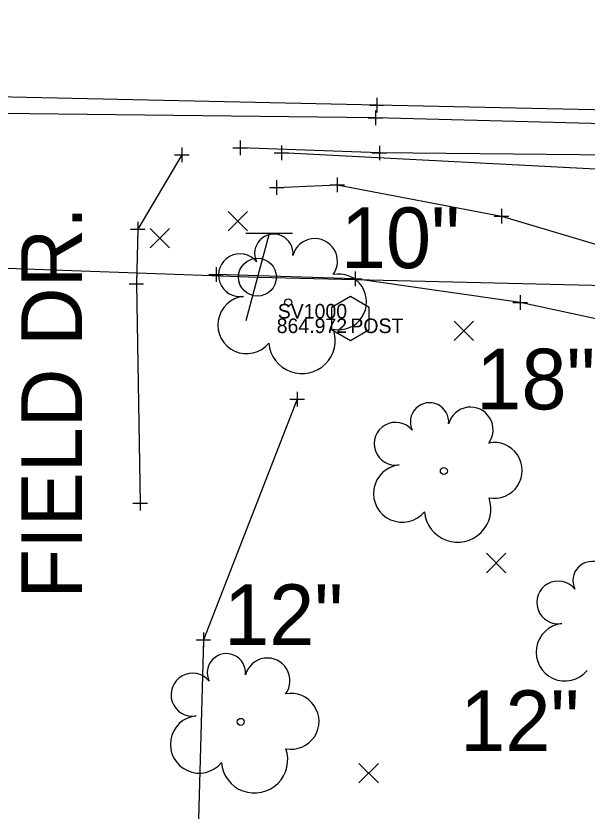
# Model space of a CAD drawing. Extents: x 2005176 to 2005823, y 572472 to 572942.
# Drawn here: x 2005452.2 to 2005491.4, y 572551.1 to 572605.7 of the extents above; entities that cross this region are included whole.
import ezdxf

# ---------------------------------------------------------------- set-up
doc = ezdxf.new("R2010")
doc.units = 0
for name, color, linetype in [('DR_X_Text', 7, 'Continuous'), ('DV_X_Property_Line', 7, 'Continuous'), ('GE_X_Alignment_100_Bearings', 7, 'Continuous'), ('GE_X_Alignment_100_Curve_Data', 7, 'Continuous'), ('GE_X_Alignment_100_Distances', 7, 'Continuous'), ('GE_X_Alignment_100_Stations', 7, 'Continuous'), ('GE_X_Alignment_500_Bearings', 7, 'Continuous'), ('PV_X_COP', 7, 'Continuous'), ('SC_Scratch1', 7, 'Continuous'), ('SC_Scratch10', 7, 'Continuous'), ('SC_Scratch8', 7, 'Continuous'), ('SV_P_Mon_Cells_Set', 7, 'Continuous'), ('SV_X_Control_Cells_Found', 7, 'Continuous'), ('SV_X_Mon_Cells_Found', 7, 'Continuous'), ('SV_X_Random_Point', 7, 'Continuous'), ('SV_X_Shot_Marker', 7, 'Continuous'), ('UT_X_Overhead_Telecom', 7, 'Continuous'), ('VG_X_Text', 7, 'Continuous')]:
    doc.layers.add(name, color=color, linetype=linetype)

msp = doc.modelspace()

# ---------------------------------------------------------------- linework, layer by layer
at = {"layer": 'GE_X_Alignment_100_Bearings'}
msp.add_lwpolyline([(2005818.636, 572588.972), (2005775.196, 572590.402), (2005728.29, 572591.88), (2005676.677, 572593.613), (2005626.55, 572595.194), (2005577.828, 572596.717), (2005526.97, 572598.442), (2005477.007, 572599.528), (2005423.668, 572600.697), (2005368.746, 572601.993), (2005321.745, 572602.994), (2005266.716, 572604.351), (2005220.033, 572605.659)], dxfattribs=at)
at = {"layer": 'GE_X_Alignment_100_Curve_Data'}
msp.add_lwpolyline([(2005463.609, 572596.115), (2005460.593, 572591.02), (2005460.492, 572587.254), (2005460.751, 572572.197)], dxfattribs=at)
at = {"layer": 'GE_X_Alignment_100_Distances'}
msp.add_lwpolyline([(2005818.697, 572589.047), (2005775.196, 572590.402), (2005728.29, 572591.88), (2005676.677, 572593.613), (2005626.55, 572595.194), (2005577.828, 572596.717), (2005526.97, 572598.442), (2005477.007, 572599.528), (2005423.668, 572600.697), (2005368.746, 572601.993), (2005321.745, 572602.994), (2005266.716, 572604.351), (2005220.057, 572605.648)], dxfattribs=at)
at = {"layer": 'GE_X_Alignment_100_Stations'}
msp.add_lwpolyline([(2005470.12, 572593.875), (2005474.272, 572594.058), (2005485.559, 572591.913), (2005494.153, 572589.341), (2005502.252, 572586.105)], dxfattribs=at)
at = {"layer": 'GE_X_Alignment_500_Bearings'}
for points in [[(2005547.792, 572586.884), (2005537.69, 572587.6), (2005528.11, 572586.874), (2005517.957, 572586.766), (2005507.009, 572591.458), (2005495.082, 572594.973), (2005470.451, 572596.25)], [(2005496.157, 572583.959), (2005486.828, 572585.976), (2005475.498, 572587.61), (2005465.973, 572587.901)], [(2005471.535, 572579.333), (2005465.091, 572562.814), (2005464.598, 572544.768), (2005464.708, 572532.148), (2005458.479, 572515.558)]]:
    msp.add_lwpolyline(points, dxfattribs=at)
at = {"layer": 'PV_X_COP'}
msp.add_lwpolyline([(2005473.882, 572584.129), (2005475.18, 572583.379), (2005476.478, 572584.129), (2005476.478, 572585.629), (2005475.18, 572586.379), (2005473.882, 572585.629), (2005473.882, 572584.129)], dxfattribs=at)
at = {"layer": 'SC_Scratch1'}
for p, q in [((2005469.604, 572590.72), (2005467.998, 572584.72)), ((2005471.204, 572590.72), (2005468.004, 572590.72))]:
    msp.add_line(p, q, dxfattribs=at)
msp.add_circle((2005468.801, 572587.72), 1.3, dxfattribs=at)
at = {"layer": 'SC_Scratch10'}
msp.add_lwpolyline([(2005818.546, 572585.941), (2005774.935, 572587.721), (2005728.191, 572589.228), (2005676.714, 572591.115), (2005626.893, 572592.621), (2005577.772, 572593.782), (2005527.621, 572595.745), (2005477.172, 572596.247), (2005467.62, 572596.601)], dxfattribs=at)
at = {"layer": 'SC_Scratch8'}
msp.add_lwpolyline([(2005818.664, 572586.636), (2005775.011, 572588.281), (2005728.162, 572589.789), (2005676.746, 572591.584), (2005626.726, 572593.575), (2005577.921, 572595.757), (2005527.418, 572597.322), (2005476.909, 572598.652), (2005423.434, 572599.267), (2005368.772, 572600.603), (2005321.591, 572601.671), (2005267.034, 572602.727), (2005220.031, 572603.934)], dxfattribs=at)
at = {"layer": 'SV_P_Mon_Cells_Set'}
for p, q in [((2005477.007, 572600.028), (2005477.007, 572599.028)), ((2005477.007, 572600.028), (2005477.007, 572599.028)), ((2005476.507, 572599.528), (2005477.507, 572599.528)), ((2005476.507, 572599.528), (2005477.507, 572599.528)), ((2005477.007, 572599.528), (2005477.007, 572599.528)), ((2005477.007, 572599.528), (2005477.007, 572599.528)), ((2005476.909, 572599.152), (2005476.909, 572598.152)), ((2005476.409, 572598.652), (2005477.409, 572598.652)), ((2005476.909, 572598.652), (2005476.909, 572598.652)), ((2005467.62, 572597.101), (2005467.62, 572596.101)), ((2005470.451, 572596.75), (2005470.451, 572595.75)), ((2005477.172, 572596.747), (2005477.172, 572595.747)), ((2005463.109, 572596.115), (2005464.109, 572596.115)), ((2005463.609, 572596.615), (2005463.609, 572595.615)), ((2005463.609, 572596.115), (2005463.609, 572596.115)), ((2005467.12, 572596.601), (2005468.12, 572596.601)), ((2005467.62, 572596.601), (2005467.62, 572596.601)), ((2005469.951, 572596.25), (2005470.951, 572596.25)), ((2005470.451, 572596.25), (2005470.451, 572596.25)), ((2005476.672, 572596.247), (2005477.672, 572596.247)), ((2005477.172, 572596.247), (2005477.172, 572596.247)), ((2005474.272, 572594.558), (2005474.272, 572593.558)), ((2005470.12, 572594.375), (2005470.12, 572593.375)), ((2005473.772, 572594.058), (2005474.772, 572594.058)), ((2005474.272, 572594.058), (2005474.272, 572594.058)), ((2005469.62, 572593.875), (2005470.62, 572593.875)), ((2005470.12, 572593.875), (2005470.12, 572593.875)), ((2005485.559, 572592.413), (2005485.559, 572591.413)), ((2005485.059, 572591.913), (2005486.059, 572591.913)), ((2005485.559, 572591.913), (2005485.559, 572591.913)), ((2005460.593, 572591.52), (2005460.593, 572590.52)), ((2005460.093, 572591.02), (2005461.093, 572591.02)), ((2005460.593, 572591.02), (2005460.593, 572591.02)), ((2005465.473, 572587.901), (2005466.473, 572587.901)), ((2005465.973, 572588.401), (2005465.973, 572587.401)), ((2005465.973, 572587.901), (2005465.973, 572587.901)), ((2005475.498, 572588.11), (2005475.498, 572587.11)), ((2005460.492, 572587.754), (2005460.492, 572586.754)), ((2005474.998, 572587.61), (2005475.998, 572587.61)), ((2005475.498, 572587.61), (2005475.498, 572587.61)), ((2005459.992, 572587.254), (2005460.992, 572587.254)), ((2005460.492, 572587.254), (2005460.492, 572587.254)), ((2005486.828, 572586.476), (2005486.828, 572585.476)), ((2005486.328, 572585.976), (2005487.328, 572585.976)), ((2005486.828, 572585.976), (2005486.828, 572585.976)), ((2005471.535, 572579.833), (2005471.535, 572578.833)), ((2005471.035, 572579.333), (2005472.035, 572579.333)), ((2005471.535, 572579.333), (2005471.535, 572579.333)), ((2005460.751, 572572.697), (2005460.751, 572571.697)), ((2005460.251, 572572.197), (2005461.251, 572572.197)), ((2005460.751, 572572.197), (2005460.751, 572572.197)), ((2005465.091, 572563.314), (2005465.091, 572562.314)), ((2005464.591, 572562.814), (2005465.591, 572562.814)), ((2005465.091, 572562.814), (2005465.091, 572562.814))]:
    msp.add_line(p, q, dxfattribs=at)
at = {"layer": 'SV_X_Random_Point'}
for p, q in [((2005466.789, 572590.889), (2005468.122, 572592.225)), ((2005466.789, 572592.225), (2005468.122, 572590.889)), ((2005461.432, 572589.726), (2005462.765, 572591.061)), ((2005461.432, 572591.061), (2005462.765, 572589.726)), ((2005482.305, 572583.367), (2005483.638, 572584.702)), ((2005482.305, 572584.702), (2005483.638, 572583.367)), ((2005484.513, 572567.422), (2005485.847, 572568.757)), ((2005484.513, 572568.757), (2005485.847, 572567.422)), ((2005475.768, 572552.984), (2005477.101, 572554.319)), ((2005475.768, 572554.319), (2005477.101, 572552.984))]:
    msp.add_line(p, q, dxfattribs=at)
at = {"layer": 'SV_X_Shot_Marker'}
for centre in [(2005470.912, 572585.986), (2005481.596, 572574.413), (2005467.653, 572557.181)]:
    msp.add_circle(centre, 0.24, dxfattribs=at)
for centre, radius, start, end in [((2005469.928, 572589.354), 1.317, 354.0047, 205.9741), ((2005472.738, 572588.815), 1.553, 323.83, 165.0376), ((2005467.602, 572587.85), 1.471, 39.0625, 279.5412), ((2005474.372, 572586.022), 1.915, 259.1453, 101.4596), ((2005468.058, 572584.437), 1.974, 96.1722, 320.5737), ((2005471.858, 572583.381), 2.284, 184.9476, 19.4572), ((2005480.613, 572577.78), 1.317, 354.0047, 205.9741), ((2005483.423, 572577.242), 1.553, 323.83, 165.0376), ((2005478.287, 572576.277), 1.471, 39.0625, 279.5412), ((2005485.057, 572574.449), 1.915, 259.1453, 101.4596), ((2005478.743, 572572.864), 1.974, 96.1722, 320.5737), ((2005482.543, 572571.808), 2.284, 184.9476, 19.4572), ((2005491.772, 572566.878), 1.317, 354.0047, 205.9741), ((2005489.446, 572565.375), 1.471, 39.0625, 279.5412), ((2005489.902, 572561.962), 1.974, 96.1722, 320.5737), ((2005466.669, 572560.549), 1.317, 354.0047, 205.9741), ((2005469.479, 572560.011), 1.553, 323.83, 165.0376), ((2005464.344, 572559.046), 1.471, 39.0625, 279.5412), ((2005471.113, 572557.217), 1.915, 259.1453, 101.4596), ((2005464.8, 572555.633), 1.974, 96.1722, 320.5737), ((2005468.599, 572554.576), 2.284, 184.9476, 19.4572)]:
    msp.add_arc(centre, radius, start, end, dxfattribs=at)
at = {"layer": 'UT_X_Overhead_Telecom'}
for p, q in [((2005321.598, 572593.022), (2005468.843, 572587.718)), ((2005468.843, 572587.718), (2005612.939, 572584.192))]:
    msp.add_line(p, q, dxfattribs=at)

# ---------------------------------------------------------------- texts
at = {"layer": 'DR_X_Text'}
msp.add_text('FIELD DR.', height=4.1667, rotation=90, dxfattribs=at).set_placement((2005456.755, 572565.65))
at = {"layer": 'DV_X_Property_Line'}
msp.add_text('POST', height=1, dxfattribs=at).set_placement((2005475.18, 572583.879))
at = {"layer": 'SV_X_Control_Cells_Found'}
msp.add_text('SV1000', height=1, dxfattribs=at).set_placement((2005470.196, 572584.879))
at = {"layer": 'SV_X_Mon_Cells_Found'}
msp.add_text('864.972', height=1, dxfattribs=at).set_placement((2005470.123, 572583.879))
at = {"layer": 'VG_X_Text'}
for s, p in [('10"', (2005474.523, 572588.337)), ('18"', (2005483.819, 572578.637)), ('12"', (2005466.508, 572562.456)), ('12"', (2005482.72, 572555.177))]:
    msp.add_text(s, height=4.1667, dxfattribs=at).set_placement(p)

doc.saveas('drawing.dxf')
